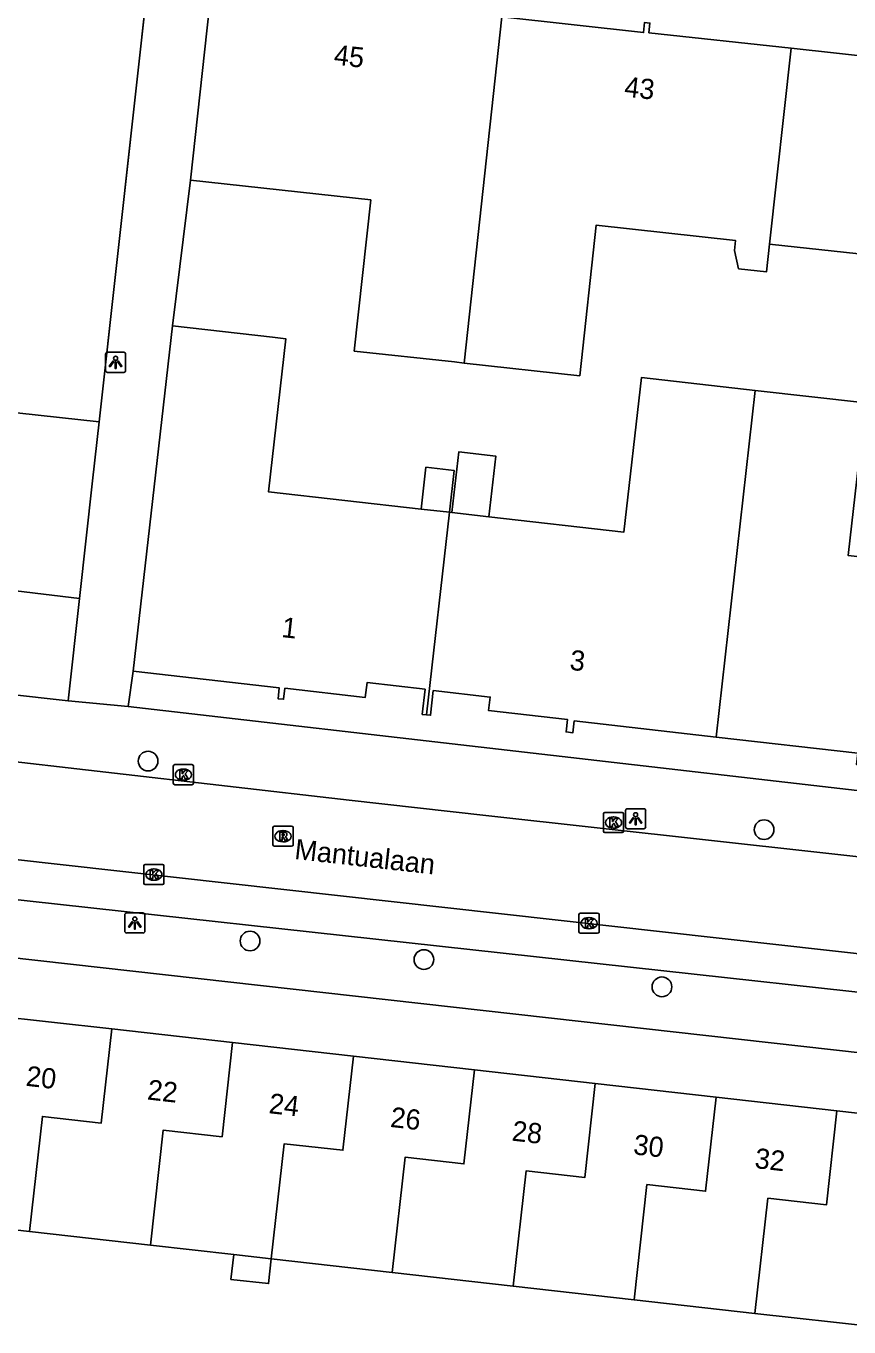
# Model space of a CAD drawing. Extents: x 162082 to 163393, y 388091 to 388632.
# Drawn here: x 162700.6 to 162741.5, y 388146 to 388210.6 of the extents above; entities that cross this region are included whole.
import ezdxf

# ---------------------------------------------------------------- set-up
doc = ezdxf.new("R2010")
doc.units = 0
for name, color, linetype in [('IMGEO_Boom', 7, 'Continuous'), ('IMGEO_Groenvoorziening', 7, 'Continuous'), ('IMGEO_Hek', 7, 'Continuous'), ('IMGEO_Kolk', 7, 'Continuous'), ('IMGEO_Lichtpunt', 7, 'Continuous'), ('IMGEO_Openbare_ruimte_label', 7, 'Continuous'), ('IMGEO_Pand', 7, 'Continuous'), ('IMGEO_Pand_nummerreeks', 7, 'Continuous'), ('IMGEO_Pand_overbouw', 7, 'Continuous'), ('IMGEO_Rijbaan_lokaal_open', 7, 'Continuous'), ('IMGEO_Rioolput', 7, 'Continuous'), ('IMGEO_Voetpad_open', 7, 'Continuous')]:
    doc.layers.add(name, color=color, linetype=linetype)

msp = doc.modelspace()

# ---------------------------------------------------------------- linework, layer by layer
at = {"layer": 'IMGEO_Boom'}
for centre in [(162706.672, 388174.085), (162737.249, 388170.682), (162711.731, 388165.158), (162720.359, 388164.238), (162732.179, 388162.883)]:
    msp.add_circle(centre, 0.489, dxfattribs=at)
at = {"layer": 'IMGEO_Groenvoorziening'}
for points in [[(162666.371, 388195.051), (162704.239, 388190.913)], [(162703.27, 388182.157), (162665.601, 388186.69)]]:
    msp.add_lwpolyline(points, dxfattribs=at)
at = {"layer": 'IMGEO_Hek'}
for points in [[(162714.001, 388278.243), (162710.804, 388250), (162708.484, 388229.124), (162704.239, 388190.917)], [(162704.239, 388190.917), (162662.426, 388195.481), (162637.2, 388198.38), (162612.235, 388201.026), (162600.069, 388202.629), (162596.208, 388203.054)]]:
    msp.add_lwpolyline(points, dxfattribs=at)
at = {"layer": 'IMGEO_Kolk'}
for p, q in [((162707.923, 388172.985), (162707.923, 388173.837)), ((162707.998, 388173.911), (162708.85, 388173.911)), ((162708.411, 388173.691), (162708.436, 388173.691)), ((162708.924, 388173.837), (162708.924, 388172.985)), ((162708.434, 388173.131), (162708.409, 388173.131)), ((162708.85, 388172.911), (162707.998, 388172.911)), ((162729.273, 388170.609), (162729.273, 388171.461)), ((162729.348, 388171.535), (162730.2, 388171.535)), ((162729.761, 388171.315), (162729.786, 388171.315)), ((162730.274, 388171.461), (162730.274, 388170.609)), ((162730.2, 388170.535), (162729.348, 388170.535)), ((162729.784, 388170.755), (162729.759, 388170.755)), ((162706.458, 388168.028), (162706.458, 388168.88)), ((162706.533, 388168.954), (162707.385, 388168.954)), ((162706.946, 388168.734), (162706.971, 388168.734)), ((162707.459, 388168.88), (162707.459, 388168.028)), ((162707.385, 388167.954), (162706.533, 388167.954)), ((162706.969, 388168.174), (162706.944, 388168.174)), ((162728.133, 388166.541), (162728.985, 388166.541)), ((162728.058, 388165.615), (162728.058, 388166.467)), ((162728.546, 388166.321), (162728.571, 388166.321)), ((162729.059, 388166.467), (162729.059, 388165.615)), ((162728.985, 388165.541), (162728.133, 388165.541)), ((162728.569, 388165.761), (162728.544, 388165.761))]:
    msp.add_line(p, q, dxfattribs=at)
for points in [[(162707.923, 388172.985), (162707.923, 388173.837)], [(162707.998, 388173.911), (162708.85, 388173.911)], [(162708.244, 388173.611), (162708.367, 388173.611), (162708.367, 388173.46), (162708.497, 388173.611), (162708.661, 388173.611), (162708.515, 388173.46), (162708.668, 388173.211), (162708.516, 388173.211), (162708.431, 388173.375), (162708.367, 388173.308), (162708.367, 388173.211), (162708.244, 388173.211), (162708.244, 388173.611)], [(162708.924, 388173.837), (162708.924, 388172.985)], [(162708.85, 388172.911), (162707.998, 388172.911)], [(162729.273, 388170.609), (162729.273, 388171.461)], [(162729.348, 388171.535), (162730.2, 388171.535)], [(162729.594, 388171.235), (162729.717, 388171.235), (162729.717, 388171.084), (162729.847, 388171.235), (162730.011, 388171.235), (162729.865, 388171.084), (162730.018, 388170.835), (162729.866, 388170.835), (162729.781, 388170.999), (162729.717, 388170.932), (162729.717, 388170.835), (162729.594, 388170.835), (162729.594, 388171.235)], [(162730.274, 388171.461), (162730.274, 388170.609)], [(162730.2, 388170.535), (162729.348, 388170.535)], [(162706.458, 388168.028), (162706.458, 388168.88)], [(162706.533, 388168.954), (162707.385, 388168.954)], [(162706.779, 388168.654), (162706.902, 388168.654), (162706.902, 388168.503), (162707.032, 388168.654), (162707.196, 388168.654), (162707.05, 388168.503), (162707.203, 388168.254), (162707.051, 388168.254), (162706.966, 388168.418), (162706.902, 388168.351), (162706.902, 388168.254), (162706.779, 388168.254), (162706.779, 388168.654)], [(162707.459, 388168.88), (162707.459, 388168.028)], [(162707.385, 388167.954), (162706.533, 388167.954)], [(162728.133, 388166.541), (162728.985, 388166.541)], [(162728.058, 388165.615), (162728.058, 388166.467)], [(162728.379, 388166.241), (162728.502, 388166.241), (162728.502, 388166.09), (162728.632, 388166.241), (162728.796, 388166.241), (162728.65, 388166.09), (162728.803, 388165.841), (162728.651, 388165.841), (162728.566, 388166.005), (162728.502, 388165.938), (162728.502, 388165.841), (162728.379, 388165.841), (162728.379, 388166.241)], [(162729.059, 388166.467), (162729.059, 388165.615)], [(162728.985, 388165.541), (162728.133, 388165.541)]]:
    msp.add_lwpolyline(points, dxfattribs=at)
for centre, start, end in [((162708, 388173.835), 91.55205, 178.44795), ((162708, 388173.835), 91.55205, 178.44795), ((162708.848, 388173.835), 1.55205, 88.44795), ((162708.848, 388173.835), 1.55205, 88.44795), ((162708, 388172.987), 181.55205, 268.44795), ((162708, 388172.987), 181.55205, 268.44795), ((162708.848, 388172.987), 271.55205, 358.44795), ((162708.848, 388172.987), 271.55205, 358.44795), ((162729.35, 388171.459), 91.55205, 178.44795), ((162729.35, 388171.459), 91.55205, 178.44795), ((162730.198, 388171.459), 1.55205, 88.44795), ((162730.198, 388171.459), 1.55205, 88.44795), ((162729.35, 388170.611), 181.55205, 268.44795), ((162729.35, 388170.611), 181.55205, 268.44795), ((162730.198, 388170.611), 271.55205, 358.44795), ((162730.198, 388170.611), 271.55205, 358.44795), ((162706.535, 388168.878), 91.55205, 178.44795), ((162706.535, 388168.878), 91.55205, 178.44795), ((162707.383, 388168.878), 1.55205, 88.44795), ((162707.383, 388168.878), 1.55205, 88.44795), ((162706.535, 388168.03), 181.55205, 268.44795), ((162706.535, 388168.03), 181.55205, 268.44795), ((162707.383, 388168.03), 271.55205, 358.44795), ((162707.383, 388168.03), 271.55205, 358.44795), ((162728.135, 388166.465), 91.55205, 178.44795), ((162728.135, 388166.465), 91.55205, 178.44795), ((162728.983, 388166.465), 1.55205, 88.44795), ((162728.983, 388166.465), 1.55205, 88.44795), ((162728.135, 388165.617), 181.55205, 268.44795), ((162728.135, 388165.617), 181.55205, 268.44795), ((162728.983, 388165.617), 271.55205, 358.44795), ((162728.983, 388165.617), 271.55205, 358.44795)]:
    msp.add_arc(centre, 0.0765, start, end, dxfattribs=at)
for centre, major_axis, ratio, start_param, end_param in [((162708.41, 388173.411), (-0.387, 0.002), 0.722429, 4.712389, 7.853982), ((162708.435, 388173.411), (-0.39, 0.002), 0.717154, 1.570796, 4.712389), ((162729.76, 388171.035), (-0.387, 0.002), 0.722429, 4.712389, 7.853982), ((162729.785, 388171.035), (-0.39, 0.002), 0.717154, 1.570796, 4.712389), ((162706.945, 388168.454), (-0.387, 0.002), 0.722429, 4.712389, 7.853982), ((162706.97, 388168.454), (-0.39, 0.002), 0.717154, 1.570796, 4.712389), ((162728.545, 388166.041), (-0.387, 0.002), 0.722429, 4.712389, 7.853982), ((162728.57, 388166.041), (-0.39, 0.002), 0.717154, 1.570796, 4.712389)]:
    msp.add_ellipse(centre, major_axis=major_axis, ratio=ratio, start_param=start_param, end_param=end_param, dxfattribs=at)
at = {"layer": 'IMGEO_Lichtpunt'}
for p, q in [((162704.559, 388194.277), (162704.559, 388193.47)), ((162704.559, 388194.277), (162704.559, 388193.47)), ((162705.461, 388194.372), (162704.653, 388194.372)), ((162705.461, 388194.372), (162704.653, 388194.372)), ((162705.555, 388193.47), (162705.555, 388194.277)), ((162705.555, 388193.47), (162705.555, 388194.277)), ((162704.653, 388193.376), (162705.461, 388193.376)), ((162704.653, 388193.376), (162705.461, 388193.376)), ((162731.275, 388171.723), (162730.467, 388171.723)), ((162731.275, 388171.723), (162730.467, 388171.723)), ((162730.373, 388171.628), (162730.373, 388170.821)), ((162730.373, 388171.628), (162730.373, 388170.821)), ((162731.369, 388170.821), (162731.369, 388171.628)), ((162731.369, 388170.821), (162731.369, 388171.628)), ((162730.467, 388170.727), (162731.275, 388170.727)), ((162730.467, 388170.727), (162731.275, 388170.727)), ((162706.416, 388166.551), (162705.608, 388166.551)), ((162706.416, 388166.551), (162705.608, 388166.551)), ((162705.514, 388166.456), (162705.514, 388165.649)), ((162705.514, 388166.456), (162705.514, 388165.649)), ((162706.51, 388165.649), (162706.51, 388166.456)), ((162706.51, 388165.649), (162706.51, 388166.456)), ((162705.608, 388165.555), (162706.416, 388165.555)), ((162705.608, 388165.555), (162706.416, 388165.555))]:
    msp.add_line(p, q, dxfattribs=at)
for points in [[(162704.933, 388193.941), (162704.972, 388193.913), (162704.784, 388193.651), (162704.746, 388193.678), (162704.933, 388193.941)], [(162705.035, 388193.893), (162705.082, 388193.893), (162705.082, 388193.571), (162705.035, 388193.571), (162705.035, 388193.893)], [(162705.145, 388193.913), (162705.183, 388193.94), (162705.37, 388193.678), (162705.331, 388193.65), (162705.145, 388193.913)], [(162730.747, 388171.292), (162730.786, 388171.264), (162730.598, 388171.002), (162730.56, 388171.029), (162730.747, 388171.292)], [(162730.849, 388171.244), (162730.896, 388171.244), (162730.896, 388170.922), (162730.849, 388170.922), (162730.849, 388171.244)], [(162730.959, 388171.264), (162730.997, 388171.291), (162731.184, 388171.029), (162731.145, 388171.001), (162730.959, 388171.264)], [(162705.888, 388166.12), (162705.927, 388166.092), (162705.739, 388165.83), (162705.701, 388165.857), (162705.888, 388166.12)], [(162705.99, 388166.072), (162706.037, 388166.072), (162706.037, 388165.75), (162705.99, 388165.75), (162705.99, 388166.072)], [(162706.1, 388166.092), (162706.138, 388166.119), (162706.325, 388165.857), (162706.286, 388165.829), (162706.1, 388166.092)]]:
    msp.add_lwpolyline(points, dxfattribs=at)
for centre in [(162705.058, 388194.075), (162730.872, 388171.426), (162706.013, 388166.254)]:
    msp.add_circle(centre, 0.0994, dxfattribs=at)
for centre, start, end in [((162704.653, 388194.277), 90, 180), ((162704.653, 388194.277), 90, 180), ((162705.461, 388194.277), 0, 90), ((162705.461, 388194.277), 0, 90), ((162704.653, 388193.47), 180, 270), ((162704.653, 388193.47), 180, 270), ((162705.461, 388193.47), 270, 0), ((162705.461, 388193.47), 270, 360), ((162730.467, 388171.628), 90, 180), ((162730.467, 388171.628), 90, 180), ((162731.275, 388171.628), 0, 90), ((162731.275, 388171.628), 0, 90), ((162730.467, 388170.821), 180, 270), ((162730.467, 388170.821), 180, 270), ((162731.275, 388170.821), 270, 0), ((162731.275, 388170.821), 270, 360), ((162705.608, 388166.456), 90, 180), ((162705.608, 388166.456), 90, 180), ((162706.416, 388166.456), 0, 90), ((162706.416, 388166.456), 0, 90), ((162705.608, 388165.649), 180, 270), ((162705.608, 388165.649), 180, 270), ((162706.416, 388165.649), 270, 0), ((162706.416, 388165.649), 270, 360)]:
    msp.add_arc(centre, 0.0946, start, end, dxfattribs=at)
at = {"layer": 'IMGEO_Pand'}
for points in [[(162708.768, 388202.91), (162709.83, 388212.61)], [(162724.237, 388211.019), (162722.353, 388193.838)], [(162738.585, 388209.46), (162731.531, 388210.232), (162731.584, 388210.712), (162731.317, 388210.742), (162731.262, 388210.233), (162724.237, 388211.019)], [(162738.585, 388209.46), (162737.519, 388199.74)], [(162752.938, 388207.858), (162745.995, 388208.607), (162746.058, 388209.176), (162745.699, 388209.216), (162745.641, 388208.688), (162738.585, 388209.46)], [(162722.353, 388193.838), (162721.873, 388193.891), (162716.902, 388194.435), (162717.722, 388201.931), (162708.768, 388202.91)], [(162737.519, 388199.74), (162737.368, 388198.365), (162735.984, 388198.517), (162735.773, 388199.418), (162735.828, 388199.925), (162728.913, 388200.681), (162728.096, 388193.21), (162722.353, 388193.838)], [(162751.056, 388190.693), (162745.568, 388191.293), (162746.386, 388198.77), (162737.519, 388199.74)], [(162707.88, 388195.679), (162706.975, 388187.702), (162705.936, 388178.541)], [(162720.225, 388186.589), (162712.643, 388187.449), (162713.504, 388195.041), (162712.849, 388195.115), (162707.88, 388195.679)], [(162736.812, 388192.477), (162731.159, 388193.118), (162730.289, 388185.448), (162723.591, 388186.207)], [(162734.864, 388175.279), (162736.812, 388192.477)], [(162736.812, 388192.477), (162742.286, 388191.856), (162741.427, 388184.283), (162750.328, 388183.273)], [(162723.591, 388186.207), (162723.932, 388189.215), (162722.09, 388189.424), (162721.749, 388186.416)], [(162721.626, 388186.43), (162721.862, 388188.508), (162720.46, 388188.667), (162720.225, 388186.589)], [(162720.225, 388186.589), (162721.626, 388186.43)], [(162721.626, 388186.43), (162720.485, 388176.38)], [(162721.749, 388186.416), (162721.626, 388186.43)], [(162723.591, 388186.207), (162721.749, 388186.416)], [(162705.936, 388178.541), (162713.185, 388177.719), (162713.124, 388177.183), (162713.4, 388177.152), (162713.462, 388177.697), (162717.454, 388177.245), (162717.537, 388177.981), (162720.421, 388177.654), (162720.279, 388176.403), (162720.485, 388176.38)], [(162720.485, 388176.38), (162720.689, 388176.357), (162720.828, 388177.584), (162723.651, 388177.263), (162723.575, 388176.588), (162727.491, 388176.144), (162727.422, 388175.53), (162727.757, 388175.492), (162727.823, 388176.077), (162734.864, 388175.279)], [(162734.864, 388175.279), (162741.906, 388174.48), (162741.841, 388173.912), (162742.147, 388173.878), (162742.211, 388174.442), (162746.216, 388173.988), (162746.306, 388174.78), (162749.099, 388174.464), (162748.953, 388173.171), (162749.178, 388173.146)], [(162704.866, 388160.792), (162698.866, 388161.469)], [(162704.866, 388160.792), (162704.343, 388156.125), (162701.422, 388156.455), (162700.78, 388150.743)], [(162710.866, 388160.116), (162704.866, 388160.792)], [(162710.866, 388160.116), (162710.344, 388155.448), (162707.425, 388155.777), (162706.783, 388150.066)], [(162716.866, 388159.439), (162710.866, 388160.116)], [(162712.786, 388149.389), (162713.427, 388155.1), (162716.343, 388154.771), (162716.866, 388159.439)], [(162722.866, 388158.762), (162716.866, 388159.439)], [(162718.788, 388148.712), (162719.428, 388154.423), (162722.344, 388154.094), (162722.866, 388158.762)], [(162728.866, 388158.085), (162722.866, 388158.762)], [(162724.791, 388148.035), (162725.43, 388153.745), (162728.343, 388153.417), (162728.866, 388158.085)], [(162728.866, 388158.085), (162734.867, 388157.408)], [(162734.867, 388157.408), (162734.344, 388152.739), (162731.432, 388153.068), (162730.793, 388147.358)], [(162740.866, 388156.732), (162734.867, 388157.408)], [(162736.796, 388146.681), (162737.434, 388152.391), (162740.343, 388152.062), (162740.866, 388156.732)], [(162746.866, 388156.055), (162740.866, 388156.732)], [(162700.78, 388150.743), (162694.777, 388151.42)], [(162706.783, 388150.066), (162700.78, 388150.743)], [(162712.786, 388149.389), (162710.922, 388149.599), (162706.783, 388150.066)], [(162718.788, 388148.712), (162712.786, 388149.389)], [(162724.791, 388148.035), (162718.788, 388148.712)], [(162730.793, 388147.358), (162724.791, 388148.035)], [(162736.796, 388146.681), (162730.793, 388147.358)], [(162742.794, 388146.004), (162736.796, 388146.681)]]:
    msp.add_lwpolyline(points, dxfattribs=at)
at = {"layer": 'IMGEO_Pand_overbouw'}
msp.add_lwpolyline([(162712.786, 388149.389), (162710.922, 388149.599), (162710.784, 388148.366), (162712.648, 388148.157)], close=True, dxfattribs=at)
at = {"layer": 'IMGEO_Rijbaan_lokaal_open'}
for points in [[(162680.392, 388176.308), (162716.658, 388172.147), (162723.437, 388171.392), (162745.54, 388168.934), (162751.96, 388168.22), (162757.203, 388167.636)], [(162753.966, 388163.189), (162694.451, 388169.835)]]:
    msp.add_lwpolyline(points, dxfattribs=at)
at = {"layer": 'IMGEO_Rioolput'}
for p, q in [((162712.868, 388169.931), (162712.868, 388170.783)), ((162712.943, 388170.857), (162713.795, 388170.857)), ((162713.356, 388170.637), (162713.381, 388170.637)), ((162713.869, 388170.783), (162713.869, 388169.931)), ((162713.795, 388169.857), (162712.943, 388169.857)), ((162713.379, 388170.077), (162713.354, 388170.077))]:
    msp.add_line(p, q, dxfattribs=at)
for points in [[(162712.868, 388169.931), (162712.868, 388170.783)], [(162712.943, 388170.857), (162713.795, 388170.857)], [(162713.457, 388170.555), (162713.205, 388170.557), (162713.205, 388170.157)], [(162713.383, 388170.476), (162713.329, 388170.476), (162713.329, 388170.395)], [(162713.329, 388170.395), (162713.381, 388170.395)], [(162713.869, 388170.783), (162713.869, 388169.931)], [(162713.795, 388169.857), (162712.943, 388169.857)], [(162713.205, 388170.157), (162713.329, 388170.157), (162713.329, 388170.319), (162713.34, 388170.319)], [(162713.387, 388170.29), (162713.458, 388170.157), (162713.598, 388170.157), (162713.533, 388170.283)]]:
    msp.add_lwpolyline(points, dxfattribs=at)
for centre, radius, start, end in [((162712.945, 388170.781), 0.0765, 91.55205, 178.44795), ((162712.945, 388170.781), 0.0765, 91.55205, 178.44795), ((162713.365, 388170.584), 0.19, 274.7715, 282.96867), ((162713.389, 388170.38), 0.0964, 77.00612, 93.18647), ((162713.403, 388170.437), 0.0378, 276.66336, 79.67722), ((162713.456, 388170.445), 0.109, 350.36119, 89.41601), ((162713.454, 388170.445), 0.112, 277.58423, 350.98172), ((162713.793, 388170.781), 0.0765, 1.55205, 88.44795), ((162713.793, 388170.781), 0.0765, 1.55205, 88.44795), ((162712.945, 388169.933), 0.0765, 181.55205, 268.44795), ((162712.945, 388169.933), 0.0765, 181.55205, 268.44795), ((162713.339, 388170.266), 0.0533, 26.02933, 88.69889), ((162713.438, 388170.23), 0.108, 29.51342, 73.79051), ((162713.793, 388169.933), 0.0765, 271.55205, 358.44795), ((162713.793, 388169.933), 0.0765, 271.55205, 358.44795)]:
    msp.add_arc(centre, radius, start, end, dxfattribs=at)
for centre, major_axis, ratio, start_param, end_param in [((162713.355, 388170.357), (-0.387, 0.002), 0.722429, 4.712389, 7.853982), ((162713.38, 388170.357), (-0.39, 0.002), 0.717154, 1.570796, 4.712389)]:
    msp.add_ellipse(centre, major_axis=major_axis, ratio=ratio, start_param=start_param, end_param=end_param, dxfattribs=at)
at = {"layer": 'IMGEO_Voetpad_open'}
for points in [[(162704.239, 388190.913), (162708.41, 388228.518), (162708.484, 388229.124)], [(162707.88, 388195.679), (162708.768, 388202.91)], [(162704.239, 388190.913), (162703.915, 388187.998), (162703.27, 388182.157)], [(162703.27, 388182.157), (162702.709, 388177.08)], [(162702.709, 388177.08), (162665.064, 388181.271)], [(162705.689, 388176.792), (162705.936, 388178.541)], [(162705.689, 388176.792), (162702.709, 388177.08)], [(162763.406, 388170.138), (162705.689, 388176.792)], [(162751.077, 388161.612), (162697.497, 388167.497)], [(162690.136, 388165.428), (162753.371, 388158.332)]]:
    msp.add_lwpolyline(points, dxfattribs=at)

# ---------------------------------------------------------------- texts
at = {"layer": 'IMGEO_Openbare_ruimte_label'}
msp.add_text('Mantualaan', height=1, rotation=353.62818, dxfattribs=at).set_placement((162713.907, 388169.232))
at = {"layer": 'IMGEO_Pand_nummerreeks'}
for s, rotation, p in [('45', 353.74291, (162715.86, 388208.649)), ('43', 353.7433, (162730.277, 388207.068)), ('1', 353.52558, (162713.266, 388180.244)), ('3', 353.52558, (162727.566, 388178.621)), ('20', 353.5643, (162700.574, 388157.976)), ('22', 353.5643, (162706.598, 388157.296)), ('24', 353.56568, (162712.632, 388156.616)), ('26', 353.5643, (162718.662, 388155.935)), ('28', 353.5643, (162724.695, 388155.255)), ('30', 353.5643, (162730.725, 388154.575)), ('32', 353.5643, (162736.749, 388153.895))]:
    msp.add_text(s, height=1, rotation=rotation, dxfattribs=at).set_placement(p)

doc.saveas('drawing.dxf')
